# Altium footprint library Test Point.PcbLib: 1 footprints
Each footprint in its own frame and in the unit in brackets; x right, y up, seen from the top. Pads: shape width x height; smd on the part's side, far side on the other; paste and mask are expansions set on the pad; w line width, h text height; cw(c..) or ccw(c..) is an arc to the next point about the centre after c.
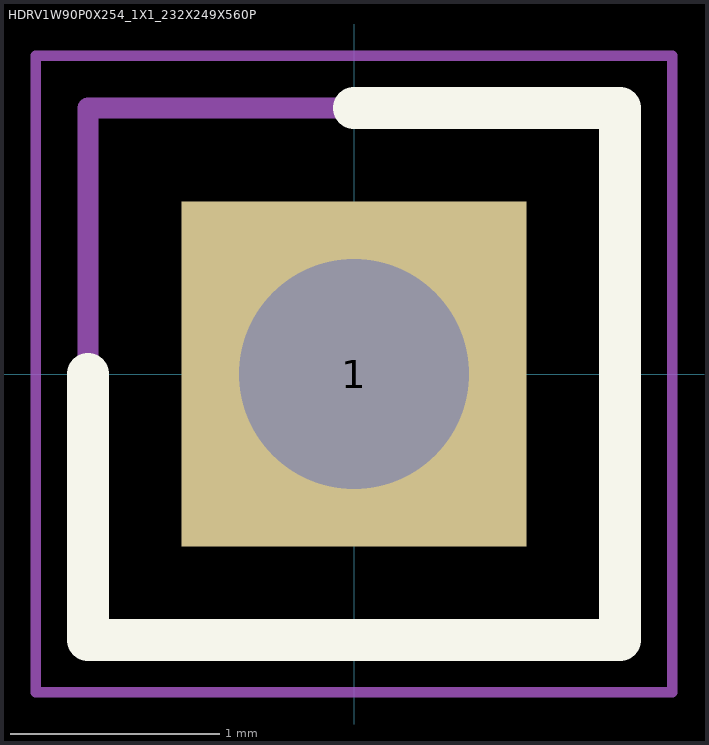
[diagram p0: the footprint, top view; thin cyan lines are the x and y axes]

## HDRV1W90P0X254_1X1_232X249X560P [mm]
pads (1):
  rect 1.65x1.65 hole 1.1: 1(0,0)
Top Overlay:
  lines w0.2: -1.27,0 -1.27,-1.27 1.27,-1.27 1.27,1.27 0,1.27
Mechanical 13:
  lines w0.1: -1.27,-1.27 -1.27,1.27 1.27,1.27 1.27,-1.27 -1.27,-1.27
Mechanical 15:
  lines w0.05: -1.52,-1.52 -1.52,1.52 1.52,1.52 1.52,-1.52 -1.52,-1.52
3D body "90120-0761.stp": height 9.25, standoff -2.87, extent -1.27,-1.25 1.27,1.25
